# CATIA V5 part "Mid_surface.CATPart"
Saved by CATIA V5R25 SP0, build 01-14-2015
Part number: Part1
Bounding box of the stored display mesh (mm): x -50 to 50, y -40.257 to 69.743, z 0 to 105
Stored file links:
  E:\cadcim\GSD_cat_v5-6r2014\Part_files\Mid_surface.CATPart
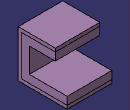
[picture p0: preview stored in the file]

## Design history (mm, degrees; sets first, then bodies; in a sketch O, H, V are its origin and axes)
Body1 (main body)
  Sketch1 on yz-plane, origin (0, 0, 0), H (0, 1, 0), V (0, 0, 1)
    point P1 (-40.2568, 105)
    line L1 (-15.2568, 80) -> (-15.2568, 25)
    line L2 (-40.2568, 0) -> (-40.2568, 105)
    point P3 (-40.2568, 0)
    point P4 (-15.2568, 25)
    line L3 (-15.2568, 25) -> (69.7432, 25)
    line L4 (69.7432, 25) -> (69.7432, 0)
    line L5 (69.7432, 0) -> (-40.2568, 0)
    point P5 (69.7432, 25)
    point P6 (69.7432, 0)
    point P7 (-40.2568, 0)
    reference intersected line E1 through (0, 0) direction (-1, 0) from xy-plane
    reference intersected line E2 through (0, 0) direction (0, 1) from zx-plane
    reference intersected line E4 through (0, 0) direction (0, 1) from zx-plane
    line L6 (-15.2568, 80) -> (43.024, 80)
    line L7 (43.024, 80) -> (43.024, 105)
    line L8 (43.024, 105) -> (-40.2568, 105)
    point P10 (-40.2568, 105)
    distance P4 P5 = 85
    distance L6 L8 = 25
    distance L8 H = 105
    vertical: L1 V, L2 V, L4 V, E2 V, E4 V, L7 V
    horizontal: L3 H, L5 H, E1 H, L6 H, L8 H
    coincidence: P6 H, E1 P3, P1 P10, P3 P7
  Set1
    Extrude1: Lim1 50, Lim2 50, Element1 Sketch1
    MidSurface1: InputSolid Extrude1, FacePairs ({midsurfacefacepair Face1 face of Extrude1 from Sketch1.L3, Face2 face of Extrude1 from Sketch1.L5}; {midsurfacefacepair Face1 face of Extrude1 from Sketch1.L1, Face2 face of Extrude1 from Sketch1.L2}; {midsurfacefacepair Face1 face of Extrude1 from Sketch1.L6, Face2 face of Extrude1 from Sketch1.L8}), OffsetRatio 0.3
